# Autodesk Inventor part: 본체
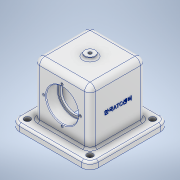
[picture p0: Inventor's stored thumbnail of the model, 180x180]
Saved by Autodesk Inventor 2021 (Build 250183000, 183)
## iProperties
Created: 2022-07
Part Number: 본체
Material: 알루미늄 6061
Document SubType Name: Modeling
Designer: cwnu10
Mass: 1059.83 g
Surface Area: 721.846 cm^2
Volume: 392.53 cm^3
Density: 2.7 g/cm^3
Appearance: 알루미늄 - 평지
Author: cwnu10
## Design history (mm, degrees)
sketch "스케치1"
  geometry: L1 (58, -58)-(-58, -58); L2 (-58, -58)-(-58, 58); L3 (-58, 58)-(58, 58); L4 (58, 58)-(58, -58); L5 (58, -58)-(-58, 58); L6 (-58, -58)-(58, 58); 1 further point
  constraints: 12 end point, 2 midpoint, 2 parallel, 2 perpendicular, 1 horizontal
  dimensions: "d0" = 116 distance of L2.end L3.end
extrude "돌출1" new body sketch "스케치1" distance "d1" = 10; taper "d2" = 0 deg
sketch "스케치2"
  geometry: L1 (41, -41)-(-41, -41); L2 (-41, -41)-(-41, 41); L3 (-41, 41)-(41, 41); L4 (41, 41)-(41, -41); L5 (41, -41)-(-41, 41); L6 (-41, -41)-(41, 41); 1 further point
  constraints: 12 end point, 2 midpoint, 2 parallel, 2 perpendicular, 1 horizontal
  dimensions: "d3" = 82 distance of L1.start L1.end
extrude "돌출2" join sketch "스케치2" distance "d4" = 90; taper "d5" = 0 deg
fillet "모깎기1" dims "d6" = 12
fillet "모깎기2" dims "d7" = 8
sketch "스케치3"
  geometry: L1 (0, -46)-(0, 46) reference; C1 r 20 at (48, 0); 2 further points
  constraints: 1 centre point, 1 horizontal alignment, 1 midpoint
  dimensions: "d8" = 40 diameter of C1; "d9" = 48 distance from line of C1.centre L1
extrude "돌출3" cut sketch "스케치3" extent not by distance; stored distance "d10" = 0; taper "d11" = 0 deg
sketch "스케치4"
  geometry: C1 r 20 at (33, 38) reference; 2 further points
  constraints: 1 coincident
hole "구멍1" sketch "스케치4" at (33, 38) diameter "d12" = 47; stored, may be unused: countersink angle "d16" = 90 deg, drill point angle "d18" = 0 deg; dims "d13" = 6, "d14" = 4, "d15" = 2, "d17" = 17
sketch "스케치5"
  geometry: C1 r 23.5 at (33, 38) reference; A1 r 27 centre (33, 38) between (33, 65) and (33, 11); 3 further points
  constraints: 4 point on circle, 2 horizontal alignment, 2 vertical alignment, 1 centre point, 1 coincident
  dimensions: "d23" = 54 diameter of A1
hole "구멍2" sketch "스케치5" at (33, 65), (33, 11), (60, 38), (6, 38) diameter "d24" = 3.242; stored, may be unused: countersink angle "d28" = 90 deg, drill point angle "d30" = 118 deg; dims "d25" = 8, "d26" = 4, "d27" = 2, "d29" = 10
fillet "모깎기4" dims "d31" = 0.6
chamfer "모따기2" distance "d32" = 1; stored, may be unused: second distance "d33" = 2, angle "d34" = 45 deg
sketch "스케치6"
  geometry: C1 r 7.5 at (0, 0); 1 further point
  constraints: 1 centre point, 1 coincident
  dimensions: "d35" = 15 diameter of C1
extrude "돌출4" join sketch "스케치6" distance "d36" = 4; taper "d37" = 0 deg
fillet "모깎기5" dims "d38" = 8
sketch "스케치7"
  geometry: L1 (-21, 30)-(21, 30); L2 (21, 30)-(21, -30); L3 (21, -30)-(-21, -30); L4 (-21, -30)-(-21, 30); L5 (-21, 30)-(21, -30); L6 (21, 30)-(-21, -30); 1 further point
  constraints: 12 end point, 2 midpoint, 2 parallel, 1 horizontal, 1 perpendicular
  dimensions: "d39" = 42 distance of L2.end L3.end; "d40" = 60 distance of L1.end L2.end
extrude "돌출5" cut sketch "스케치7" distance "d41" = 80; taper "d42" = 0 deg
fillet "모깎기6" dims "d43" = 3
fillet "모깎기7" dims "d44" = 3
sketch "스케치8"
  geometry: A1 r 12 centre (-46, 46) between (-46, 58) and (-58, 46) reference; A2 r 12 centre (46, 46) between (58, 46) and (46, 58) reference; A3 r 12 centre (46, -46) between (46, -58) and (58, -46) reference; A4 r 12 centre (-46, -46) between (-58, -46) and (-46, -58) reference; 1 further point
hole "구멍3" sketch "스케치8" at (-46, -46), (-46, 46), (46, 46), (46, -46) diameter "d45" = 9; stored, may be unused: countersink angle "d49" = 90 deg, drill point angle "d51" = 0 deg; dims "d46" = 8, "d47" = 4, "d48" = 2, "d50" = 10
sketch "스케치9"
  geometry: C1 r 7.5 at (0, 0) reference; 2 further points
  constraints: 1 coincident
hole "구멍4" sketch "스케치9" at (0, 0) diameter "d52" = 4.917; stored, may be unused: countersink angle "d56" = 90 deg, drill point angle "d58" = 0 deg; dims "d53" = 12, "d54" = 4, "d55" = 2, "d57" = 10
sketch "스케치10"
  geometry: L1 (-13, -82)-(79, -82) reference; 3 further points
  constraints: 1 midpoint, 1 vertical alignment, 1 other
  dimensions: "d59" = 48 distance of point (33, -82) point (33, -34)
extrude "돌출6" join sketch "스케치10" distance "d60" = 0.5; taper "d61" = 0 deg
node "솔리드1"
mirror "미러1"
feature "A9D066F2-1C7D-4E18-AEED-F7BC21143FA4" dims "d12" = 47, "d13" = 6, "d14" = 4, "d15" = 2, "d16" = 90 deg, "d17" = 17, "d18" = 0
